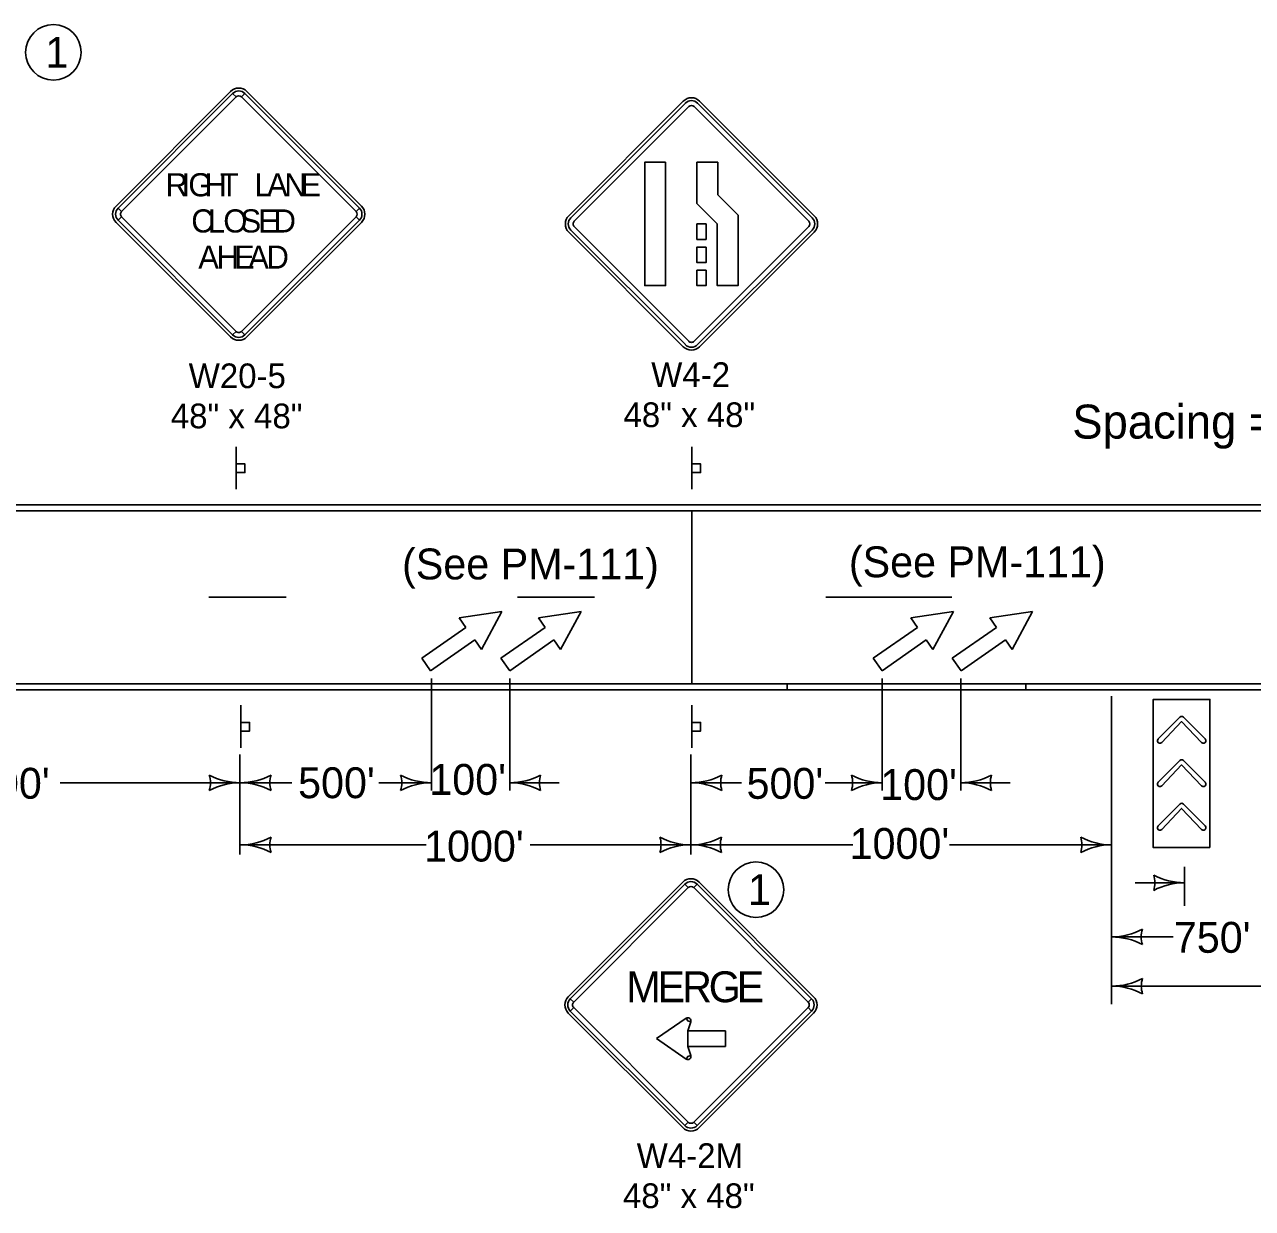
# Model space of a CAD drawing. Extents: x 10133 to 2270741, y 5363 to 1733450.
# Drawn here: x 28936 to 29731, y 6340 to 7107 of the extents above; entities that cross this region are included whole.
import ezdxf

# ---------------------------------------------------------------- set-up
doc = ezdxf.new("R2010")
doc.units = 0
for name, color, linetype in [('dsnNonPlotable', 7, 'Continuous'), ('dsnShtPlotShapeBatchPrint', 7, 'Continuous'), ('dsnStdBorder', 7, 'Continuous'), ('Level 12', 7, 'Continuous'), ('Level 2', 7, 'Continuous')]:
    doc.layers.add(name, color=color, linetype=linetype)

msp = doc.modelspace()

# ---------------------------------------------------------------- linework, layer by layer
at = {"layer": 'dsnNonPlotable'}
for p, q in [((29244.99, 6726.6), (29217.35, 6722.5)), ((29231.68, 6702.03), (29244.99, 6726.6)), ((29296.3, 6726.6), (29268.65, 6722.5)), ((29282.99, 6702.03), (29296.3, 6726.6)), ((29537.63, 6726.6), (29509.98, 6722.5)), ((29524.32, 6702.03), (29537.63, 6726.6)), ((29588.94, 6726.6), (29561.3, 6722.5)), ((29575.63, 6702.03), (29588.94, 6726.6)), ((29217.35, 6722.5), (29221.65, 6716.36)), ((29268.65, 6722.5), (29272.95, 6716.36)), ((29509.98, 6722.5), (29514.28, 6716.36)), ((29561.3, 6722.5), (29565.6, 6716.36)), ((29221.65, 6716.36), (29192.98, 6696.29)), ((29272.95, 6716.36), (29244.29, 6696.29)), ((29514.28, 6716.36), (29485.62, 6696.29)), ((29565.6, 6716.36), (29536.93, 6696.29)), ((29198.72, 6688.1), (29227.38, 6708.17)), ((29227.38, 6708.17), (29231.68, 6702.03)), ((29250.02, 6688.1), (29278.69, 6708.17)), ((29278.69, 6708.17), (29282.99, 6702.03)), ((29491.36, 6688.1), (29520.02, 6708.17)), ((29520.02, 6708.17), (29524.32, 6702.03)), ((29542.67, 6688.1), (29571.33, 6708.17)), ((29571.33, 6708.17), (29575.63, 6702.03)), ((29192.98, 6696.29), (29198.72, 6688.1)), ((29244.29, 6696.29), (29250.02, 6688.1)), ((29485.62, 6696.29), (29491.36, 6688.1)), ((29536.93, 6696.29), (29542.67, 6688.1)), ((28158.76, 6679.83), (29774.05, 6679.83))]:
    msp.add_line(p, q, dxfattribs=at)
for points in [[(28150.78, 6791.83), (30180.37, 6791.83)], [(29055.03, 6735.82), (29105.02, 6735.82)], [(29255, 6735.82), (29304.99, 6735.82)], [(29255, 6735.82), (29304.99, 6735.82)], [(29454.97, 6735.82), (29504.96, 6735.82)], [(29486.72, 6735.82), (29536.72, 6735.82)]]:
    msp.add_lwpolyline(points, dxfattribs=at)
at = {"layer": 'dsnShtPlotShapeBatchPrint'}
for centre in [(28954.23, 7088.95), (29409.63, 6546.33)]:
    msp.add_circle(centre, 18, dxfattribs=at)
at = {"layer": 'dsnStdBorder'}
for p, q in [((29069.08, 7063.63), (28994.84, 6989.38)), ((29070.41, 7062.31), (29072.62, 7060.1)), ((29076.15, 7060.1), (29078.36, 7062.31)), ((29153.94, 6989.38), (29079.69, 7063.63)), ((29288.29, 6983.08), (29362.54, 7057.33)), ((29362.54, 7057.32), (29288.29, 6983.08)), ((29363.87, 7056), (29289.62, 6981.75)), ((29291.83, 6979.54), (29366.08, 7053.79)), ((29369.61, 7053.79), (29369.61, 7053.79)), ((29369.61, 7053.79), (29443.86, 6979.54)), ((29446.07, 6981.75), (29371.82, 7056)), ((29373.15, 7057.33), (29447.4, 6983.08)), ((29373.15, 7057.32), (29373.15, 7057.33)), ((29447.4, 6983.08), (29373.15, 7057.32)), ((28998.37, 6985.85), (28996.16, 6988.06)), ((28996.16, 6980.1), (28998.37, 6982.31)), ((29152.61, 6988.06), (29150.4, 6985.85)), ((29150.4, 6982.31), (29152.61, 6980.1)), ((28994.84, 6978.78), (29069.08, 6904.53)), ((29079.69, 6904.53), (29153.94, 6978.78)), ((29289.62, 6973.8), (29363.87, 6899.55)), ((29366.08, 6901.76), (29291.83, 6976.01)), ((29443.86, 6976.01), (29369.61, 6901.76)), ((29371.82, 6899.55), (29446.07, 6973.8)), ((29288.29, 6972.47), (29362.54, 6898.22)), ((29362.54, 6898.22), (29288.29, 6972.47)), ((29373.15, 6898.22), (29447.4, 6972.47)), ((29447.4, 6972.47), (29373.15, 6898.22)), ((29072.62, 6908.07), (29070.41, 6905.86)), ((29078.36, 6905.86), (29076.15, 6908.07)), ((29072.63, 6805.83), (29072.63, 6833.33)), ((29368.02, 6805.83), (29368.02, 6833.33)), ((29075.73, 6638.33), (29075.73, 6665.83)), ((29368.02, 6638.33), (29368.02, 6665.83)), ((29686.78, 6658.11), (29700.87, 6644.02)), ((29686.78, 6630.05), (29700.87, 6615.95)), ((29686.78, 6601.81), (29700.87, 6587.72)), ((29362.2, 6551.26), (29287.95, 6477.01)), ((29447.05, 6477.01), (29372.8, 6551.26)), ((29363.52, 6549.93), (29365.73, 6547.72)), ((29369.27, 6547.72), (29371.48, 6549.93)), ((29291.48, 6473.47), (29289.28, 6475.68)), ((29445.72, 6475.68), (29443.51, 6473.47)), ((29287.95, 6466.4), (29362.2, 6392.16)), ((29289.28, 6467.73), (29291.48, 6469.94)), ((29372.8, 6392.16), (29447.05, 6466.4)), ((29443.51, 6469.94), (29445.72, 6467.73)), ((29364.38, 6463.11), (29365.47, 6461.39)), ((29365.47, 6461.39), (29367.39, 6460.75)), ((29365.47, 6438.27), (29364.38, 6436.55)), ((29367.39, 6438.92), (29365.47, 6438.27)), ((29365.73, 6395.69), (29363.52, 6393.48)), ((29371.48, 6393.48), (29369.27, 6395.69))]:
    msp.add_line(p, q, dxfattribs=at)
for points in [[(29070.41, 7062.31), (28996.16, 6988.06), (28998.37, 6985.85), (29072.62, 7060.1), (29070.41, 7062.31)], [(29152.61, 6988.06), (29078.36, 7062.31), (29076.15, 7060.1), (29150.4, 6985.85), (29152.61, 6988.06)], [(29351.09, 7017.77), (29351.09, 6937.77), (29337.59, 6937.77), (29337.59, 7017.77)], [(29384.85, 6996.62), (29398.1, 6983.37), (29398.1, 6937.77), (29384.6, 6937.77), (29384.6, 6977.77), (29371.34, 6991.03), (29371.34, 7017.77), (29384.85, 7017.77)], [(28996.16, 6980.1), (29070.41, 6905.86), (29072.62, 6908.07), (28998.37, 6982.31), (28996.16, 6980.1)], [(29078.36, 6905.86), (29152.61, 6980.1), (29150.4, 6982.31), (29076.15, 6908.07), (29078.36, 6905.86)], [(29377.34, 6977.77), (29371.34, 6977.77), (29371.34, 6967.77), (29377.34, 6967.77)], [(29377.34, 6962.77), (29371.34, 6962.77), (29371.34, 6952.77), (29377.34, 6952.77)], [(29377.34, 6947.77), (29371.34, 6947.77), (29371.34, 6937.77), (29377.34, 6937.77)], [(29072.73, 6822.27), (29072.73, 6816.65), (29078.35, 6816.65), (29078.35, 6822.27)], [(29368.11, 6822.27), (29368.11, 6816.65), (29373.74, 6816.65), (29373.74, 6822.27)], [(29703.95, 6573.67), (29703.95, 6669.67), (29667.24, 6669.67), (29667.24, 6573.67)], [(29075.83, 6654.77), (29075.83, 6649.15), (29081.45, 6649.15), (29081.45, 6654.77)], [(29368.11, 6654.77), (29368.11, 6649.15), (29373.74, 6649.15), (29373.74, 6654.77)], [(29363.52, 6549.93), (29289.28, 6475.68), (29291.48, 6473.47), (29365.73, 6547.72), (29363.52, 6549.93)], [(29445.72, 6475.68), (29371.48, 6549.93), (29369.27, 6547.72), (29443.51, 6473.47), (29445.72, 6475.68)], [(29289.28, 6467.73), (29363.52, 6393.48), (29365.73, 6395.69), (29291.48, 6469.94), (29289.28, 6467.73)], [(29371.48, 6393.48), (29445.72, 6467.73), (29443.51, 6469.94), (29369.27, 6395.69), (29371.48, 6393.48)], [(29345.16, 6449.83), (29364.38, 6436.55), (29365.47, 6438.27), (29367.39, 6438.92), (29365.4, 6444.83), (29365.4, 6454.83), (29367.39, 6460.75), (29365.47, 6461.39), (29364.38, 6463.11), (29345.16, 6449.83)], [(29389.84, 6454.83), (29389.84, 6444.83), (29365.4, 6444.83), (29365.4, 6454.83), (29389.84, 6454.83)]]:
    msp.add_lwpolyline(points, close=True, dxfattribs=at)
for points in [[(29289.62, 6981.75), (29363.87, 7056)], [(29291.83, 6979.54), (29366.08, 7053.79)], [(29369.61, 7053.79), (29443.86, 6979.54)], [(29371.82, 7056), (29446.07, 6981.75)], [(29363.87, 6899.55), (29289.62, 6973.8)], [(29366.08, 6901.76), (29291.83, 6976.01)], [(29443.86, 6976.01), (29369.61, 6901.76)], [(29446.07, 6973.8), (29371.82, 6899.55)], [(29670.29, 6643.99), (29670.34, 6644.04), (29684.42, 6658.12), (29684.44, 6658.14)], [(29698.55, 6641.68), (29698.49, 6641.75), (29685.6, 6655.32), (29672.69, 6641.73)], [(29670.29, 6615.92), (29670.34, 6615.97), (29684.42, 6630.06), (29684.44, 6630.07)], [(29698.55, 6613.62), (29698.49, 6613.68), (29685.6, 6627.25), (29672.69, 6613.67)], [(29670.29, 6587.69), (29670.34, 6587.74), (29684.42, 6601.82), (29684.44, 6601.84)], [(29698.55, 6585.38), (29698.49, 6585.45), (29685.6, 6599.02), (29672.69, 6585.43)]]:
    msp.add_lwpolyline(points, dxfattribs=at)
for centre, radius, start, end in [((29074.39, 7058.33), 7.5, 44.99999, 134.99974), ((29074.39, 7058.33), 5.62, 44.99999, 134.99974), ((29074.39, 7058.33), 2.5, 44.99999, 134.99974), ((29367.84, 7052.02), 7.5, 44.99999, 134.99974), ((29367.84, 7052.02), 7.5, 44.99999, 134.99974), ((29367.84, 7052.02), 5.63, 44.99999, 134.99974), ((29367.84, 7052.02), 5.63, 44.99999, 134.99974), ((29367.84, 7052.02), 2.5, 44.99999, 134.99974), ((29367.84, 7052.02), 2.5, 44.99999, 134.99974), ((29000.14, 6984.08), 7.5, 134.99974, 224.99995), ((29148.63, 6984.08), 7.5, 315.00016, 44.9998), ((29000.14, 6984.08), 5.62, 134.99974, 224.99995), ((29000.14, 6984.08), 2.5, 134.99974, 224.99995), ((29148.63, 6984.08), 2.5, 315.00016, 44.9998), ((29148.63, 6984.08), 5.62, 315.00016, 44.9998), ((29293.6, 6977.77), 7.5, 134.99974, 224.99995), ((29293.6, 6977.77), 7.5, 134.99974, 224.99995), ((29293.6, 6977.77), 5.63, 134.99974, 224.99995), ((29293.6, 6977.77), 5.63, 134.99974, 224.99995), ((29442.09, 6977.77), 5.63, 315.00016, 44.9998), ((29442.09, 6977.77), 5.63, 315.00016, 44.9998), ((29442.09, 6977.77), 7.5, 315.00016, 44.9998), ((29442.09, 6977.77), 7.5, 315.00016, 44.9998), ((29293.6, 6977.77), 2.5, 134.99974, 224.99995), ((29293.6, 6977.77), 2.5, 134.99974, 224.99995), ((29442.09, 6977.77), 2.5, 315.00016, 44.9998), ((29442.09, 6977.77), 2.5, 315.00016, 44.9998), ((29074.39, 6909.84), 7.5, 224.99995, 315.00016), ((29074.39, 6909.84), 5.62, 224.99995, 315.00016), ((29074.39, 6909.84), 2.5, 224.99995, 315.00016), ((29367.84, 6903.53), 2.5, 224.99995, 315.00016), ((29367.84, 6903.53), 2.5, 224.99995, 315.00016), ((29367.84, 6903.53), 7.5, 224.99995, 315.00016), ((29367.84, 6903.53), 7.5, 224.99995, 315.00016), ((29367.84, 6903.53), 5.63, 224.99995, 315.00016), ((29367.84, 6903.53), 5.63, 224.99995, 315.00016), ((29685.6, 6656.97), 1.65, 44.16156, 134.60983), ((29671.48, 6642.85), 1.65, 136.201, 317.36018), ((29699.71, 6642.85), 1.65, 225.09746, 45.28103), ((29685.6, 6628.9), 1.65, 44.16156, 134.60983), ((29671.48, 6614.78), 1.65, 136.201, 317.36018), ((29699.71, 6614.78), 1.65, 225.09746, 45.28103), ((29685.6, 6600.67), 1.65, 44.16156, 134.60983), ((29671.48, 6586.55), 1.65, 136.201, 317.36018), ((29699.71, 6586.55), 1.65, 225.09746, 45.28103), ((29367.5, 6545.95), 7.5, 44.99999, 134.99974), ((29367.5, 6545.95), 5.62, 44.99999, 134.99974), ((29367.5, 6545.95), 2.5, 44.99999, 134.99974), ((29293.25, 6471.71), 7.5, 134.99974, 224.99995), ((29293.25, 6471.71), 5.62, 134.99974, 224.99995), ((29293.25, 6471.71), 2.5, 134.99974, 224.99995), ((29441.74, 6471.71), 2.5, 315.00016, 44.9998), ((29441.74, 6471.71), 5.62, 315.00016, 44.9998), ((29441.74, 6471.71), 7.5, 315.00016, 44.9998), ((29365.47, 6461.39), 2.03, 341.41867, 122.31243), ((29365.47, 6438.27), 2.03, 237.68753, 18.58186), ((29367.5, 6397.46), 7.5, 224.99995, 315.00016), ((29367.5, 6397.46), 5.62, 224.99995, 315.00016), ((29367.5, 6397.46), 2.5, 224.99995, 315.00016)]:
    msp.add_arc(centre, radius, start, end, dxfattribs=at)
at = {"layer": 'Level 12'}
for p, q in [((29199.26, 6683.19), (29199.26, 6610.59)), ((29250.07, 6683.19), (29250.07, 6610.59)), ((29491.55, 6683.19), (29491.55, 6610.59)), ((29542.36, 6683.19), (29542.36, 6610.59)), ((29640.22, 6671.7), (29640.22, 6472.19)), ((29075.08, 6634.06), (29075.08, 6569.25)), ((29367.36, 6634.06), (29367.36, 6569.25)), ((28958.68, 6615.65), (29075.08, 6615.65)), ((29075.88, 6615.65), (29108.88, 6615.65)), ((29165.24, 6615.65), (29199.26, 6615.65)), ((29250.07, 6615.65), (29282.07, 6615.65)), ((29368.17, 6615.65), (29400.29, 6615.65)), ((29454.5, 6615.65), (29491.55, 6615.65)), ((29542.36, 6615.65), (29574.36, 6615.65)), ((29075.08, 6575.42), (29195.82, 6575.42)), ((29263.38, 6575.42), (29367.36, 6575.42)), ((29472.36, 6575.42), (29367.36, 6575.42)), ((29535.19, 6575.42), (29640.19, 6575.42)), ((29687.48, 6561.08), (29687.48, 6535.95)), ((29655.48, 6550.87), (29687.48, 6550.87)), ((29640.19, 6515.75), (29680.19, 6515.75)), ((29847.94, 6483.87), (29640.25, 6483.87))]:
    msp.add_line(p, q, dxfattribs=at)
for centre, radius, start, end in [((29039.65, 6615.65), 16.42, 342.26665, 17.73335), ((29075.28, 6658.15), 42.5, 241.92751, 270), ((29075.28, 6573.15), 42.5, 90, 118.07249), ((29075.28, 6658.15), 42.5, 270, 298.07249), ((29075.28, 6573.15), 42.5, 61.92751, 90), ((29110.92, 6615.65), 16.42, 162.26665, 197.73335), ((29163.62, 6615.65), 16.42, 342.26665, 17.73335), ((29199.26, 6658.15), 42.5, 241.92751, 270), ((29199.26, 6573.15), 42.5, 90, 118.07249), ((29250.07, 6658.15), 42.5, 270, 298.07249), ((29250.07, 6573.15), 42.5, 61.92751, 90), ((29285.71, 6615.65), 16.42, 162.26665, 197.73335), ((29367.57, 6658.15), 42.5, 270, 298.07249), ((29367.57, 6573.15), 42.5, 61.92751, 90), ((29403.21, 6615.65), 16.42, 162.26665, 197.73335), ((29455.91, 6615.65), 16.42, 342.26665, 17.73335), ((29491.55, 6658.15), 42.5, 241.92751, 270), ((29491.55, 6573.15), 42.5, 90, 118.07249), ((29542.36, 6658.15), 42.5, 270, 298.07249), ((29542.36, 6573.15), 42.5, 61.92751, 90), ((29578, 6615.65), 16.42, 162.26665, 197.73335), ((29075.28, 6617.92), 42.5, 270, 298.07249), ((29075.28, 6532.92), 42.5, 61.92751, 90), ((29110.92, 6575.42), 16.42, 162.26665, 197.73335), ((29331.72, 6575.42), 16.42, 342.26665, 17.73335), ((29367.36, 6617.92), 42.5, 241.92751, 270), ((29367.36, 6532.92), 42.5, 90, 118.07249), ((29367.36, 6617.92), 42.5, 270, 298.07249), ((29367.36, 6532.92), 42.5, 61.92751, 90), ((29402.99, 6575.42), 16.42, 162.26665, 197.73335), ((29604.55, 6575.42), 16.42, 342.26665, 17.73335), ((29640.19, 6617.92), 42.5, 241.92751, 270), ((29640.19, 6532.92), 42.5, 90, 118.07249), ((29651.84, 6550.87), 16.42, 342.26665, 17.73335), ((29687.48, 6593.37), 42.5, 241.92751, 270), ((29687.48, 6508.37), 42.5, 90, 118.07249), ((29640.19, 6558.25), 42.5, 270, 298.07249), ((29675.82, 6515.75), 16.42, 162.26665, 197.73335), ((29640.19, 6473.25), 42.5, 61.92751, 90), ((29640.25, 6526.37), 42.5, 270, 298.07249), ((29675.88, 6483.87), 16.42, 162.26665, 197.73335), ((29640.25, 6441.37), 42.5, 61.92751, 90)]:
    msp.add_arc(centre, radius, start, end, dxfattribs=at)
at = {"layer": 'Level 2'}
for p, q in [((28150.78, 6791.83), (29368.02, 6791.83)), ((28150.78, 6791.83), (29946.34, 6791.83)), ((29944.62, 6795.82), (28154.78, 6795.83)), ((28154.78, 6795.82), (30281.4, 6795.82)), ((29368.02, 6791.83), (29368.02, 6679.83)), ((29946.34, 6791.83), (29368.02, 6791.83)), ((29368.02, 6791.83), (29368.02, 6679.83)), ((29199.26, 6679.83), (29199.26, 6675.83)), ((29199.26, 6675.83), (29199.26, 6679.83)), ((29199.26, 6679.83), (29250.07, 6679.83)), ((29491.55, 6679.83), (29250.07, 6679.83)), ((29250.07, 6679.83), (29250.07, 6675.83)), ((29250.07, 6679.83), (29250.07, 6675.83)), ((29368.02, 6679.83), (29429.88, 6679.83)), ((29429.88, 6679.83), (29584.52, 6679.83)), ((29584.52, 6679.83), (29429.88, 6679.83)), ((29429.88, 6679.83), (29429.88, 6675.83)), ((29429.88, 6675.83), (29429.88, 6679.83)), ((29429.88, 6679.83), (29584.52, 6679.83)), ((29491.55, 6675.83), (29491.55, 6679.83)), ((29584.52, 6675.83), (29584.52, 6679.83)), ((29584.52, 6679.83), (29584.52, 6675.83)), ((29584.52, 6679.83), (29825.43, 6679.83)), ((29825.43, 6679.83), (29584.52, 6679.83)), ((29584.52, 6679.83), (29584.52, 6675.83)), ((28154.78, 6675.83), (30486.98, 6675.83)), ((29199.26, 6675.83), (28154.78, 6675.83)), ((29250.07, 6675.83), (29199.26, 6675.83)), ((29250.07, 6675.83), (29491.55, 6675.83)), ((29584.52, 6675.83), (29429.88, 6675.83)), ((29429.88, 6675.83), (29584.52, 6675.83)), ((29584.52, 6675.83), (30415.17, 6675.83))]:
    msp.add_line(p, q, dxfattribs=at)
msp.add_lwpolyline([(29368.02, 6679.83), (29250.07, 6679.83), (29199.26, 6679.83)], dxfattribs=at)

# ---------------------------------------------------------------- texts
at = {"layer": 'dsnShtPlotShapeBatchPrint'}
for p in [(28949.03, 7078.95), (29404.43, 6536.33)]:
    msp.add_text('1', height=20, dxfattribs=at).set_placement(p)
at = {"layer": 'dsnStdBorder'}
for s, height, p in [('R', 15, (29026.9, 6995.64)), ('I', 15, (29037.35, 6995.64)), ('G', 15, (29041.7, 6995.64)), ('H', 15, (29052.14, 6995.64)), ('T', 15, (29062.15, 6995.64)), ('L', 15, (29084.65, 6995.64)), ('A', 15, (29092.75, 6995.64)), ('N', 15, (29103.92, 6995.64)), ('E', 15, (29114.37, 6995.64)), ('C', 15, (29043.6, 6972.21)), ('L', 15, (29054.34, 6972.21)), ('O', 15, (29064.37, 6972.21)), ('S', 15, (29075.57, 6972.21)), ('E', 15, (29086.94, 6972.21)), ('D', 15, (29096.97, 6972.21)), ('A', 15, (29048.14, 6948.77)), ('H', 15, (29060.03, 6948.77)), ('E', 15, (29071.36, 6948.77)), ('A', 15, (29080.54, 6948.77)), ('D', 15, (29092.42, 6948.77)), ('W20-5', 16, (29041.92, 6871.34)), ('W4-2', 16, (29341.74, 6872.1)), ('48" x 48"', 16, (29030.32, 6845.34)), ('48" x 48"', 16, (29323.78, 6846.1)), ('(See PM-111)', 20, (29180.25, 6747.42)), ('(See PM-111)', 20, (29469.88, 6748.81)), ('M', 20, (29325.62, 6473.43)), ('E', 20, (29345.82, 6473.43)), ('R', 20, (29361.8, 6473.43)), ('G', 20, (29379.02, 6473.43)), ('E', 20, (29397.19, 6473.43)), ('W4-2M', 16, (29332.33, 6366.04)), ('48" x 48"', 16, (29323.43, 6340.04))]:
    msp.add_text(s, height=height, dxfattribs=at).set_placement(p)
at = {"layer": 'Level 12'}
for s, height, p in [('Spacing = D', 22, (29614.72, 6838.67)), ("800'", 20, (28902.09, 6605.32)), ("500'", 20, (29112.84, 6605.65)), ("100'", 20, (29197.9, 6607.82)), ("500'", 20, (29403.55, 6605.25)), ("100'", 20, (29490.19, 6604.46)), ("1000'", 20, (29194.51, 6564.6)), ("1000'", 20, (29470.36, 6566.32)), ("750'", 20, (29680.54, 6505.48))]:
    msp.add_text(s, height=height, dxfattribs=at).set_placement(p)

doc.saveas('drawing.dxf')
